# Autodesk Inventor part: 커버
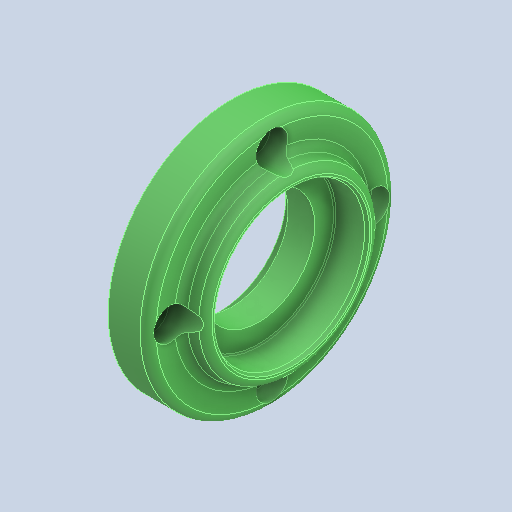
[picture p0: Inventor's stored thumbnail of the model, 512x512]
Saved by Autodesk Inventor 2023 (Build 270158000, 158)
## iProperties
Created: 2025-03
Part Number: 커버
Material: 알루미늄 6061
Document SubType Name: Modeling
Designer: ADMIN_PC
Density: 2.71 g/cm^3
Appearance: 기본값
Author: jhkim
Sending System: Autodesk Inventor 2025
Preprocessor: ST-DEVELOPER v20
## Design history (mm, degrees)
feature "솔리드1"
node "솔리드2"
